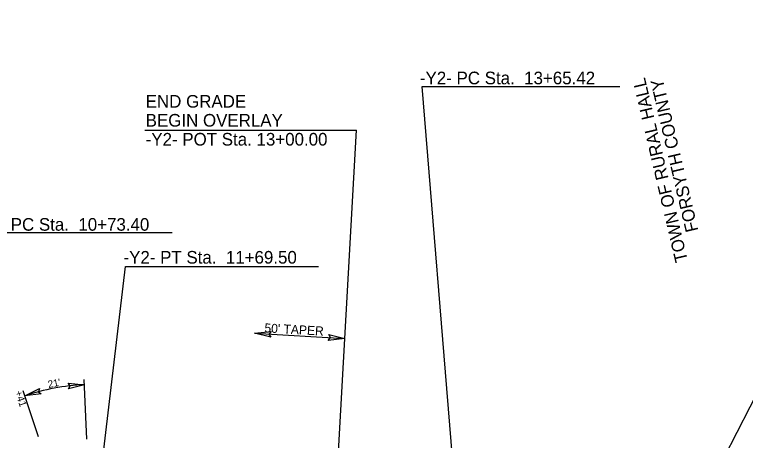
# Model space of a CAD drawing. Extents: x 1616561 to 1622460, y 896726 to 899651.
# Drawn here: x 1619580.2 to 1619984.9, y 898221.7 to 898457.6 of the extents above; entities that cross this region are included whole.
import ezdxf

# ---------------------------------------------------------------- set-up
doc = ezdxf.new("R2010")
doc.units = 0
for name, color, linetype in [('Old_Level_3', 7, 'Continuous'), ('Prop Dimension', 7, 'Continuous'), ('Prop DSN Text', 7, 'Continuous'), ('Prop Terminator CELL', 7, 'Continuous'), ('Sheet Cutting Line CELL', 7, 'Continuous'), ('Sheet North Arrow CELL', 7, 'Continuous'), ('Sheet Sticker Preliminary CELL', 7, 'Continuous')]:
    doc.layers.add(name, color=color, linetype=linetype)

msp = doc.modelspace()

# ---------------------------------------------------------------- linework, layer by layer
at = {"layer": 'Old_Level_3'}
msp.add_arc((1619799.51, 898841.24), 808.75, 229.34838, 255.58792, dxfattribs=at)
at = {"layer": 'Prop Dimension'}
msp.add_line((1619713.1, 898281.03), (1619763.02, 898278.24), dxfattribs=at)
at = {"layer": 'Prop Terminator CELL'}
for points in [[(1619722, 898278.98), (1619713.1, 898281.03), (1619722.22, 898282.12), (1619720.99, 898280.59)], [(1619754.12, 898280.29), (1619763.02, 898278.24), (1619753.9, 898277.15), (1619755.13, 898278.68)], [(1619609.75, 898253.44), (1619618.83, 898252.53), (1619609.92, 898250.3), (1619610.95, 898251.97)], [(1619594.84, 898247.46), (1619585.77, 898246.37), (1619593.99, 898250.49), (1619593.34, 898248.63)]]:
    msp.add_lwpolyline(points, close=True, dxfattribs=at)
at = {"layer": 'Sheet Cutting Line CELL'}
for centre, radius, start, end in [((1617411.12, 898000.42), 2624.02, 8.00579, 15.75048), ((1619799.51, 898841.24), 800, 229.34838, 270)]:
    msp.add_arc(centre, radius, start, end, dxfattribs=at)
at = {"layer": 'Sheet North Arrow CELL'}
for p, q in [((1619823.96, 898196.1), (1619805.89, 898417.67)), ((1619805.89, 898417.67), (1619915.36, 898417.67)), ((1619652.31, 898393.5), (1619769.46, 898393.5)), ((1619758.65, 898199.95), (1619769.46, 898393.5)), ((1620060.42, 898383.63), (1619918.08, 898104.12)), ((1619558.52, 898336.82), (1619667.41, 898336.82)), ((1619628.34, 898207.02), (1619641.63, 898318.02)), ((1619641.63, 898318.02), (1619748.55, 898318.02))]:
    msp.add_line(p, q, dxfattribs=at)
at = {"layer": 'Sheet Sticker Preliminary CELL'}
for p, q in [((1619620.16, 898222.49), (1619618.7, 898255.53)), ((1619593.36, 898223.79), (1619584.82, 898249.22))]:
    msp.add_line(p, q, dxfattribs=at)
msp.add_arc((1619624.16, 898132.14), 120.51, 92.5307, 108.5735, dxfattribs=at)

# ---------------------------------------------------------------- texts
at = {"layer": 'Prop Dimension'}
msp.add_text("50' TAPER", height=5, rotation=356.8045, dxfattribs=at).set_placement((1619718.44, 898281.58))
at = {"layer": 'Prop DSN Text'}
for s, p in [('TOWN OF RURAL HALL', (1619953.12, 898321.27)), ('FORSYTH COUNTY', (1619958.91, 898338.01))]:
    msp.add_text(s, height=7, rotation=103.1842, dxfattribs=at).set_placement(p)
at = {"layer": 'Sheet North Arrow CELL'}
for s, p in [('-Y2- PC Sta.  13+65.42', (1619804.66, 898418.97)), ('END GRADE', (1619652.77, 898406.03)), ('BEGIN OVERLAY', (1619652.77, 898395.53)), ('-Y2- POT Sta. 13+00.00', (1619652.77, 898385.03)), ('-Y2- PC Sta.  10+73.40', (1619557.73, 898337.86)), ('-Y2- PT Sta.  11+69.50', (1619640.48, 898319.64))]:
    msp.add_text(s, height=7, rotation=360, dxfattribs=at).set_placement(p)
at = {"layer": 'Sheet Sticker Preliminary CELL'}
for s, rotation, p in [("21'", 11.2995, (1619599.03, 898250.75)), ('+41', 288.0991, (1619580.32, 898248.55))]:
    msp.add_text(s, height=4, rotation=rotation, dxfattribs=at).set_placement(p)

doc.saveas('drawing.dxf')
